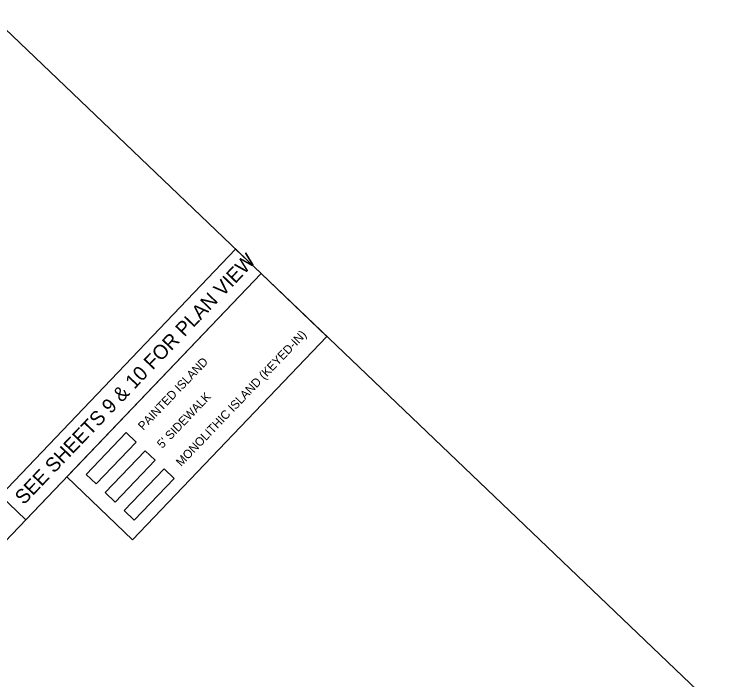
# Model space of a CAD drawing. Extents: x 2326836 to 2328631, y 602012 to 603789.
# Drawn here: x 2328051 to 2328631, y 603129 to 603670 of the extents above; entities that cross this region are included whole.
import ezdxf

# ---------------------------------------------------------------- set-up
doc = ezdxf.new("R2010")
doc.units = 0
for name, color, linetype in [('Default', 7, 'Continuous'), ('Prop Conc 4in Sidewalk', 7, 'Continuous'), ('Prop Conc 5in Monolithic Keyed In Island', 7, 'Continuous'), ('Prop Dimension Text', 7, 'Continuous'), ('Prop Lane Lines', 7, 'Continuous'), ('Sheet Plan CELL', 7, 'Continuous')]:
    doc.layers.add(name, color=color, linetype=linetype)

msp = doc.modelspace()

# ---------------------------------------------------------------- linework, layer by layer
at = {"layer": 'Default'}
for points in [[(2328039.83, 603279.08), (2328231.12, 603479.27), (2328251.83, 603459.47), (2328060.55, 603259.29)], [(2328147.26, 603243.06), (2328305.25, 603408.41), (2328251.83, 603459.46), (2328093.83, 603294.11)]]:
    msp.add_lwpolyline(points, close=True, dxfattribs=at)
at = {"layer": 'Prop Conc 4in Sidewalk'}
msp.add_lwpolyline([(2328125.03, 603281.45), (2328157.53, 603315.46), (2328165.69, 603307.66), (2328133.2, 603273.65)], close=True, dxfattribs=at)
at = {"layer": 'Prop Conc 5in Monolithic Keyed In Island'}
msp.add_lwpolyline([(2328140.43, 603266.74), (2328172.92, 603300.75), (2328181.09, 603292.95), (2328148.59, 603258.94)], close=True, dxfattribs=at)
at = {"layer": 'Prop Lane Lines'}
msp.add_lwpolyline([(2328109.63, 603296.16), (2328142.13, 603330.18), (2328150.3, 603322.37), (2328117.8, 603288.36)], close=True, dxfattribs=at)
msp.add_lwpolyline([(2328117.8, 603288.36), (2328150.3, 603322.37), (2328142.13, 603330.18), (2328109.63, 603296.16), (2328117.8, 603288.36)], dxfattribs=at)
at = {"layer": 'Sheet Plan CELL'}
for points in [[(2326835.98, 602737.58), (2327550.28, 603485.23), (2327577.17, 603459.54), (2327678.48, 603565.59), (2327746, 603501.08), (2327828.41, 603587.34), (2327892.92, 603525.71), (2328031.11, 603670.36), (2328251.83, 603459.46), (2327215.55, 602374.93)], [(2327215.55, 602374.93), (2328251.82, 603459.46), (2328631.38, 603096.8), (2327595.1, 602012.27)]]:
    msp.add_lwpolyline(points, close=True, dxfattribs=at)

# ---------------------------------------------------------------- texts
at = {"layer": 'Default'}
msp.add_text('SEE SHEETS 9 & 10 FOR PLAN VIEW', height=11.6664, rotation=46.30318, dxfattribs=at).set_placement((2328058.87, 603270.86))
at = {"layer": 'Prop Dimension Text'}
for s, p in [('MONOLITHIC ISLAND (KEYED-IN)', (2328186.91, 603302.14)), ('PAINTED ISLAND', (2328156.11, 603331.57)), ("5' SIDEWALK", (2328171.51, 603316.86))]:
    msp.add_text(s, height=7, rotation=46.30317, dxfattribs=at).set_placement(p)

doc.saveas('drawing.dxf')
